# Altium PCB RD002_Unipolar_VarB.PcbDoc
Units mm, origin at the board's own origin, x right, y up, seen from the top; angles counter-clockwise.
Board outline 40 x 14 mm, 2 copper layers (Top Layer, Bottom Layer), stack 1.37 mm thick; 29 components, 15 nets, 67 pads, 26 vias.
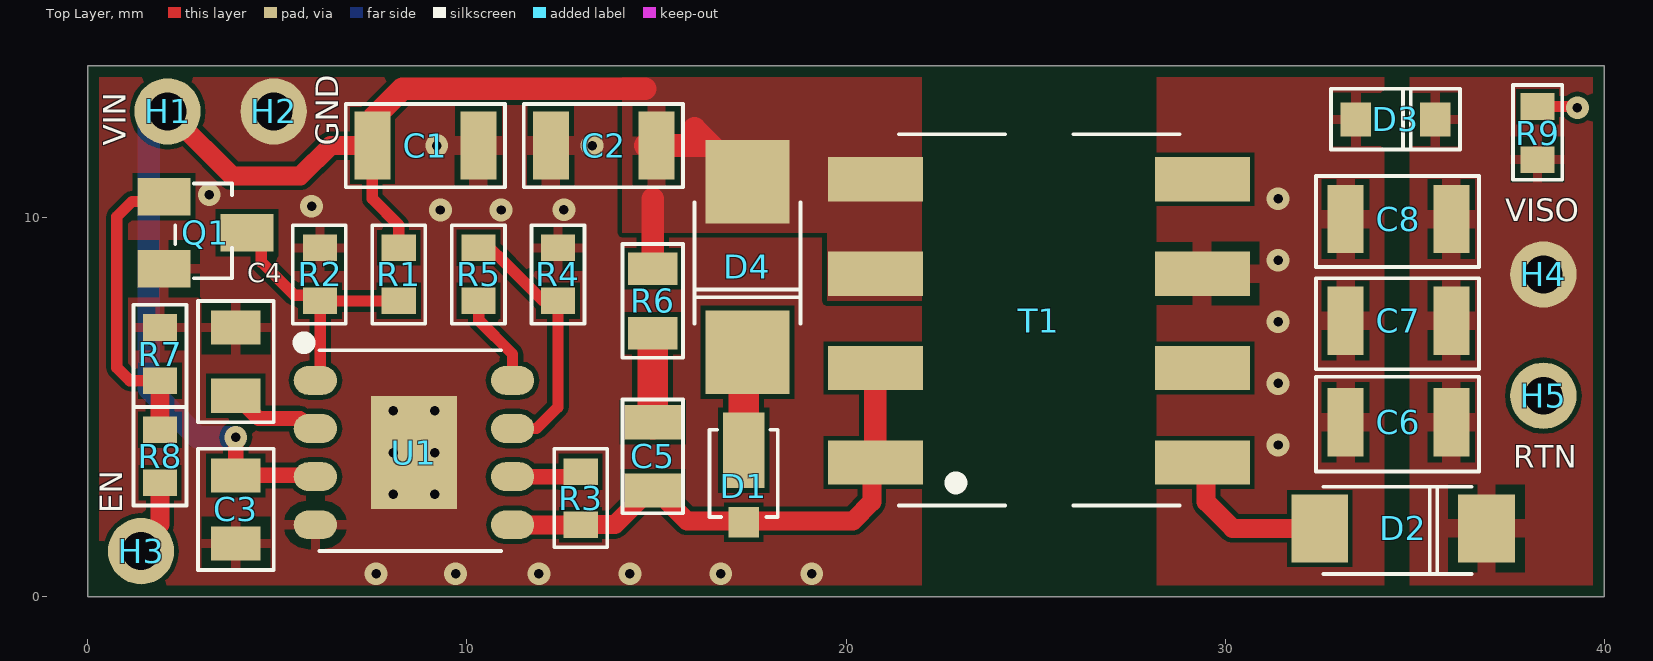
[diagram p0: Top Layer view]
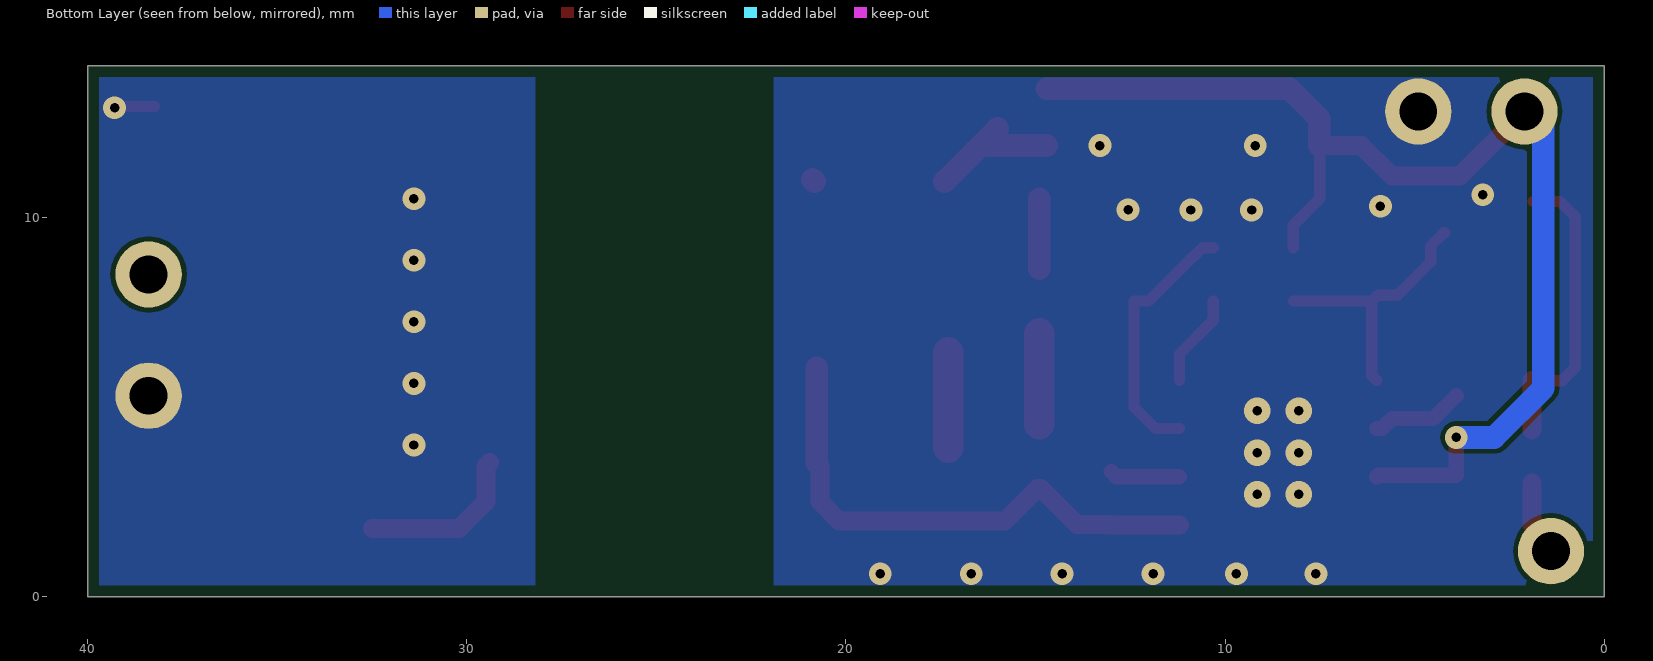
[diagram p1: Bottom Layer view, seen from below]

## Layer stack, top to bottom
Top Solder: solder mask 0.0254, SM-001, Dk 4
Top Layer: signal copper 0.035
Dielectric 1: core 1.3, Core-043, Dk 4.3
Bottom Layer: signal copper 0.035
Bottom Solder: solder mask 0.0254, SM-001, Dk 4

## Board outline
0,0 40,0 40,14 0,14

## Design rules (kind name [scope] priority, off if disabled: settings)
AcuteAngle [All] p1 off: minimum=4.50000000000000E+0001 checktracksonly=FALSE
AssemblyTestPointUsage [All] p1 off: valid=2
AssemblyTestpoint [All] p1 off: testpointundercomponent=TRUE minsize=1.016 maxsize=2.54 preferedsize=1.524 minholesize=0 maxholesize=1.016 preferedholesize=0.813 testpointgrid=0.025 usegrid=TRUE gridtolerance=0 allowsidetop=TRUE allowsidebottom=TRUE
Clearance Clearance_WEDirekt_125u_35u [All] p1: gap=0.125 ignorepadtopadclearanceinfootprint=TRUE except(0.17: SMDPad-SMDPad SMDPad-THPad THPad-THPad)
ComponentClearance "Schematic Component Clearance Constraint 2" [InComponent('NT1')] p1: gap=0 collisioncheckmode=3 verticalgap=0 showdistances=FALSE
ComponentClearance "Schematic Component Clearance Constraint 1" [InComponent('NT2')] p2: gap=0 collisioncheckmode=3 verticalgap=0 showdistances=FALSE
ComponentClearance ComponentClearance_ScrewToNut [(HasFootprint('NY PMS 440 0025 PH')) vs (HasFootprint('Keystone_1902C'))] p3: gap=0 collisioncheckmode=3 verticalgap=0 showdistances=FALSE
ComponentClearance ComponentClearance_testpoint [(HasFootprint('NO BOM TP'))] p4: gap=0 collisioncheckmode=3 verticalgap=0 showdistances=FALSE
ComponentClearance not_comp_1 [WithinRoom('not_comp')] p5: gap=0 collisioncheckmode=3 verticalgap=0 showdistances=FALSE
ComponentClearance ComponentClearance_1 [All] p6: gap=0.254 collisioncheckmode=3 verticalgap=0.254 showdistances=FALSE
ComponentClearance ComponentClearance_Shunt [InComponentClass('Header') vs InComponentClass('Shunt')] p7 off: gap=0 collisioncheckmode=3 verticalgap=0 showdistances=FALSE
ComponentClearance ComponentClearance_Logo [InComponentClass('Logo')] p8: gap=1.27 collisioncheckmode=3 verticalgap=0.254 showdistances=FALSE
ComponentClearance ComponentClearance_MountingHoles [InComponentClass('Mounting Holes')] p9: gap=0 collisioncheckmode=3 verticalgap=2540 showdistances=FALSE
ComponentClearance ComponentClearance_SmallPassives [HasFootprint('0201*') or HasFootprint('0402*') or HasFootprint('0508') or HasFootprint('0603*') or HasFootprint('0612') or HasFootprint('0805*') or HasFootprint('0815*') or HasFootprint('0830*') or HasFootprint('1206*') or HasFootprint('1210*') or HasFootprint('1808*') or HasFootprint('1812*') or HasFootprint('1825*') or HasFootprint('2010*') or HasFootprint('2220*') or HasFootprint('2225*') or HasFootprint('2512*') or HasFootprint('2728*') or HasFootprint('3518*') vs HasFootprint('0201*') or HasFootprint('0402*') or HasFootprint('0508') or HasFootprint('0603*') or HasFootprint('0612') or HasFootprint('0805*') or HasFootprint('0815*') or HasFootprint('0830*') or HasFootprint('1206*') or HasFootprint('1210*') or HasFootprint('1808*') or HasFootprint('1812*') or HasFootprint('1825*') or HasFootprint('2010*') or HasFootprint('2220*') or HasFootprint('2225*') or HasFootprint('2512*') or HasFootprint('2728*') or HasFootprint('3518*')] p10: gap=0.127 collisioncheckmode=3 verticalgap=0.254 showdistances=FALSE
ComponentClearance ComponentClearance_THtoSMT [IsThruComponent vs IsSMTComponent] p11: gap=1.016 collisioncheckmode=3 verticalgap=0.762 showdistances=FALSE
ComponentClearance ComponentClearance_THtoTH [IsThruComponent vs IsThruComponent] p12: gap=3 collisioncheckmode=3 verticalgap=0.762 showdistances=FALSE
DiffPairsRouting [All] p1 off: maxlimit=2.54 minlimit=0.254 mostfreqgap=0.254 toplayer_minwidth=0.381 toplayer_maxwidth=0.381 toplayer_prefwidth=0.381 bottomlayer_minwidth=0.381 bottomlayer_maxwidth=0.381 bottomlayer_prefwidth=0.381 maxuncoupledlength=25.4
FabricationTestPointUsage TestPointUsage [All] p1: valid=2 allowmultiple=FALSE
FabricationTestpoint Testpoint [All] p1: side=3 testpointundercomponent=TRUE minsize=1.016 maxsize=2.54 preferedsize=1.524 minholesize=0 maxholesize=1.016 preferedholesize=0.813 testpointgrid=0.025 allowsidetop=TRUE allowsidebottom=TRUE usegrid=TRUE gridtolerance=0
FanoutControl Fanout_LCC [IsLCC] p1 off: bgadir=Out bgaviamode=Centered fanoutstyle=Auto fanoutdirection=Alternating viagrid=0.025 // Fanout_LCC (Default Rule)
FanoutControl Fanout_BGA [IsBGA] p2: bgadir=Out bgaviamode=Centered fanoutstyle=Auto fanoutdirection=Alternating viagrid=0.025 // Fanout_BGA (Default Rule)
FanoutControl Fanout_Default [All] p4: bgadir=Out bgaviamode=Centered fanoutstyle=Auto fanoutdirection=Alternating viagrid=0.025 // Fanout_Default (Default Rule)
FanoutControl Fanout_Small [(CompPinCount < 5)] p5: bgadir=Out bgaviamode=Centered fanoutstyle=Auto fanoutdirection=OutThenIn viagrid=0.025 // Fanout_Small (Default Rule)
Height [All] p1 off: minheight=0 maxheight=25.4 prefheight=12.7
HoleSize [All] p1: absolutevalues=TRUE maxlimit=1000 minlimit=0.1 maxpercent=80.000 minpercent=20.000
HoleToHoleClearance [All] p1: gap=0.4 allowstackedmicrovias=TRUE
MinimumAnnularRing MinimumAnnularRing_ThermalPadVias [IsVia and InAnyComponent] p1: minimumring=0.174
MinimumAnnularRing [All] p2: minimumring=0.174
MinimumSolderMaskSliver MinimumSolderMaskSliver_Logo [InComponentClass('Logo') vs InComponentClass('Logo')] p1: minsoldermaskwidth=0.018
MinimumSolderMaskSliver [All] p2: minsoldermaskwidth=0.025
PlaneConnect [All] p1: planeconnectstyle=Direct reliefexpansion=0.254 reliefentries=4 reliefconductorwidth=0.254 reliefairgap=0.254
PolygonConnect PolygonConnect_1 [InNet('GND')] p1: connectstyle=Relief reliefconductorwidth=0.254 reliefentries=4 polygonreliefangle="90 Angle" airgapwidth=0.254
PolygonConnect [All] p2: connectstyle=Direct reliefconductorwidth=0.254 reliefentries=4 polygonreliefangle="90 Angle" airgapwidth=0.254
RoutingVias Vias_WEDirekt_125u_35u [IsVia and InAnyComponent] p1: holewidth=0.1 width=0.45 viastyle="Through Hole" minholewidth=0.1 minwidth=0.45 maxholewidth=1 maxwidth=20
RoutingVias [All] p2: holewidth=0.1 width=0.45 viastyle="Through Hole" minholewidth=0.1 minwidth=0.45 maxholewidth=20 maxwidth=20
SMDToCorner [All] p1: distance=30000
SilkToSilkClearance [All] p1 off: silktosilkclearance=0.127
SilkToSolderMaskClearance SilkscreenOverComponentPads [IsPad] p1 off: minsilkscreentomaskgap=0.127 clearancetoexposedcopper=TRUE
SolderMaskExpansion [All] p1: expansion=0.1 istentingtop=FALSE
UnRoutedNet [All] p1: checkbadconnections=TRUE
Width Width_WEDirekt_125u_35u [All] p1: maxlimit=20 minlimit=0.125 preferedwidth=0.5 minimp=50.000000 maximp=50.000000 favimp=50.000000 checkconnectedcopper=TRUE
12 further rules are at their usual default settings.

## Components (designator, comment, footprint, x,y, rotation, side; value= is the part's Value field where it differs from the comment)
C1 "885012108022" C1206 8.9,11.9 r0 top value=10u
C2 "885012108022" C1206 13.6,11.9 r0 top value=10u
C3 "885012207103" C0805#1 3.9,2.3 r90 top value=1u
C4 "885012207103" C0805#1 3.9,6.2 r270 top value=1u
C5 "885012207084" C0805#2 14.9,3.7 r90 top value=470p
C6 "885012108022" C1206 34.57,4.6 r0 top value=10u
C7 "885012108022" C1206 34.57,7.28 r0 top value=10u
C8 "885012108022" C1206 34.57,9.96 r0 top value=10u
D1 "V1PM10-M3" D_DO-219AD_(uSMP) 17.3,3.1 r270 top
D2 "VSSAF3M10-M3" D_DO-221AC_(SMA_Slim) 34.7,1.8 r0 top
D3 "PLZ16BG3H" D_DO-219AC_(uSMF) 34.5,12.6 r0 top
D4 "BZG03C27-M3" D_DO-214AC_(SMA) 17.4,8.7 r270 top
H1 "TH-1MM" PIN-TH-ROUND-1MM#1 2,12.6 r90 top
H2 "TH-1MM" PIN-TH-ROUND-1MM#2 4.7,12.6 r90 top
H3 "TH-1MM" PIN-TH-ROUND-1MM#3 1.4,1.2 r90 top
H4 "TH-1MM" PIN-TH-ROUND-1MM#3 38.4,8.5 r90 top
H5 "TH-1MM" PIN-TH-ROUND-1MM#3 38.4,5.3 r90 top
Q1 "SQ2318AES-T1_BE3" IC_SOT23-3_V 3.1,9.6 r0 top
R1 "RC0603FR-07806KL" R0603 8.2,8.5 r90 top value=806k
R2 "RC0603FR-07232KL" R0603 6.125,8.5 r270 top value=232k
R3 "RT0603FRE0771K5L" R0603 13,2.6 r270 top value=71.5k
R4 "RT0603BRD0710KL" R0603 12.4,8.5 r270 top value=10k
R5 "R0603_DNP" R0603_DNP 10.308,8.5 r90 top value=DNP
R6 "CMP0805-FX-1000ELF" R0805 14.9,7.8 r90 top value=100
R7 "RC0603FR-0710KL" R0603 1.9,6.4 r270 top value=10k
R8 "RC0603FR-073R3L" R0603 1.9,3.7 r90 top value=3.3
R9 "R0603_DNP" R0603_DNP 38.246,12.231 r270 top value=DNP
T1 "750318114" EP7_Extended_Rail 25.085,7.275 r0 top
U1 "LT8302HS8E#WPBF" LT-S8E-8_V 8.6,3.8 r0 top

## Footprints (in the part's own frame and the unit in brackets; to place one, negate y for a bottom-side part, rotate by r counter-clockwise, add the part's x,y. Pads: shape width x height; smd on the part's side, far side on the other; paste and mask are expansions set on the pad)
C0805#1 [mm] "Chip Capacitor, 2-Leads, Body 2.00x1.25mm, IPC Low Density"
  rect 0.9x1.3 smd: 1(-0.9,0) 2(0.9,0)
  body extent -1.1,-0.72 1.1,0.72, height 1.45
C0805#2 [mm] "Chip Capacitor, 2-Leads, Body 2.00x1.25mm, IPC Low Density"
  rect 0.9x1.5 smd: 1(-0.9,0) 2(0.9,0)
  body extent -1.1,-0.72 1.1,0.72, height 1.45
C1206 [mm]
  rect 0.95x1.8 smd: 1(-1.39,0) 2(1.4,0)
  body extent -1.7,-0.9 1.7,0.9, height 1.8
D_DO-214AC_(SMA) [mm] "DO-214AC SMA"
  rect 2.2x2.21 smd paste+0 mask+0: A(-2.25,0) C(2.25,0)
  body extent -3.45,-1.5 3.45,1.5, height 0.25
D_DO-219AC_(uSMF) [mm]
  rect 0.8x0.9 smd: A(-1.05,-0.01) C(1.05,-0.01)
  body extent -1.26,-0.66 1.24,0.64, height 0.6
D_DO-219AD_(uSMP) [mil]
  rect 31.5x31.5 smd: A(44.8,0)
  rect 78.74x43.31 smd: C(-30,0)
  body extent -73,-31 65,31, height 10
D_DO-221AC_(SMA_Slim) [mm] "2-Leads, Body 4.2x2.6mm"
  rect 1.5x1.8 smd: A(-2.2,0) C(2.2,0)
  body extent -2.55,-1.3 2.55,1.3, height 1.1
EP7_Extended_Rail [mm] "SMD, 8-Leads, Body 9.8x7.0mm (max), Pitch 2.49mm, IPC Medium Density"
  rect 2.5x1.17 smd: 1(-4.31,-3.735) 2(-4.31,-1.245) 3(-4.31,1.245) 4(-4.31,3.735) 5(4.32,3.735) 6(4.32,1.245) 7(4.32,-1.245) 8(4.32,-3.735)
  body extent -5.06,-5.65 5.04,5.45, height 11.39
IC_SOT23-3_V [mm] "SOT23, 3-Leads, Body 3.12x1.5mm, Pitch 0.95mm"
  rect 1.4x1 smd: 1(-1.1,0.95) 2(-1.1,-0.95) 3(1.1,0)
  body extent -1.35,-1.56 1.35,1.56, height 1.2
LT-S8E-8_V [mm] "SOIC, 8-Leads, Body 4.9x3.9mm, Pitch 1.27mm, Thermal Pad 3.25x2.26mm, Recommended"
  oval 1.143x0.76 smd: 1(-2.602,1.905) 2(-2.602,0.635) 3(-2.602,-0.635) 4(-2.602,-1.905) 5(2.601,-1.905) 6(2.601,-0.635) 7(2.601,0.635) 8(2.601,1.905)
  rect 2.26x2.99 smd paste-5: 9(0,0)
  body extent -3.01,-2.45 3.01,2.45, height 1.75
PIN-TH-ROUND-1MM#1 [mm] "PIN-TH-ROUND-1MM"
  round 1.75 hole 1: 1(0.2,-0.1)
PIN-TH-ROUND-1MM#2 [mm] "PIN-TH-ROUND-1MM"
  round 1.75 hole 1: 1(0.2,-0.2)
PIN-TH-ROUND-1MM#3 [mm] "PIN-TH-ROUND-1MM"
  round 1.75 hole 1: 1(0,0)
R0603 [mm] "Chip Resistor, Body 1.6x0.8mm, IPC High Density"
  rect 0.7x0.9 smd: 1(-0.7,0) 2(0.7,0)
  body extent -0.85,-0.47 0.85,0.47, height 0.6
R0603_DNP [mm] "Chip Resistor, Body 1.6x0.8mm, IPC High Density"
  rect 0.7x0.9 smd: 1(-0.7,0) 2(0.7,0)
R0805 [mm] "Chip Resistor, Body 2.0x1.3mm, IPC High Density"
  rect 0.85x1.3 smd: 1(-0.85,0) 2(0.85,0)
  body extent -1.1,-0.67 1.1,0.68, height 0.7

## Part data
C1 C2 C6 C7 C8: "MLCC 10uF 50V 10% X7R 1206 General Purpose", MFR="Wurth Elektronik", Package=1206, Voltage=50V
C3 C4: "MLCC 1uF 50V 10% X7R 0805 General Purpose", DC-Voltage=50V, Dielectric=X7R, MFR="Wurth Elektronik", Package=0805, Tolerance=10%
C5: "MLCC SMD 470p 50V 10% X7R 0805 General Purpose", MFR="Wurth Elektronik"
D1: "Schottky Rectifier 1A 100V SMD DO-219AD (uSMP) V1PM10-M3", Current=1A, MFR=Vishay, Package="DO-219AD (uSMP)", Voltage=100V
D2: "Schottky Rectifier 3A 100V SMD DO-221AC (SMA_Slim) VSSAF3M10-M3", Current=3A, MFR=Vishay, Package="DO-221AC (SMA Slim)", Voltage=100V
D3: "Zener 16V 0.5W SMD DO-219AC (uSMF) PLZ16BG3H", MFR=Vishay, Package="DO-219AC (uSMF)", Power=0.5W, Voltage=16V
D4: "Zener 27V 3W DO-214AC (SMA) BZG03C27-M3", MFR=Vishay, Package="DO-214AC (SMA)", Power=3W, Voltage=27V
H1 H2 H3 H4 H5: library part Pin_hole_1mm, "not available"
Q1: "N-Channel MOSFET 40 V SOT23-3", MFR=Vishay
R1: "Thick Film Resistors 806k 1% 0.1W", Case-EIA=0603, Case-Metric=1608, MFR=Yageo, Power="0.1 W", Tolerance="1 %"
R2: "Thick Film Resistors 232k 1% 0.1W", Case-EIA=0603, Case-Metric=1608, MFR=Yageo, Power="0.1 W", Tolerance="1 %"
R3: "Thin Film Resistors 71.5k 0.1% 0.1W 0603 RT0603FRE0771K5L", Case-EIA=0603, Case-Metric=1608, MFR=Yageo, Power="0.1 W", Tolerance="0.1 %"
R4: "Thin Film Resistors 10k 0.1% 0.1W", Case-EIA=0603, Case-Metric=1608, MFR=Yageo, Power="0.1 W", Tolerance="0.1 %"
R5 R9: "Footprint R0603 DNP"
R6: "Thick Film 100 5% 0.5W 0805 High Power CMP0805-FX-1000ELF", Case-EIA=0805, MFR=Bourns, Power="0.5 W", Tolerance="5 %"
R7: "Thick Film Resistors 10k 1% 0.1W", Case-EIA=0603, Case-Metric=1608, MFR=Yageo, Power="0.1 W", Tolerance="1 %"
R8: "Thick Film Resistors 3.3 1% 0.1W", Case-EIA=0603, Case-Metric=1608, MFR=Yageo, Power="0.1 W", Tolerance="1 %"
T1: "WE-AGDT Auxiliary Gate Drive Transformer, EP7, SMT, 9-18Vin, 19Vout, 6W", Input Voltage=9-18V, Interwinding Capacitance=6.8pF, MFR="Wurth Elektronik", Operating Temperature="-40 to +130degC", Output Power=6W, Output Voltage=19V, Switching Frequency=350kHz
U1: "Micropower No-Opto Isolated Flyback Converter, 2.8 to 42 V, -40 to 150 degC, 8-Pin SOIC (S8E), RoHS, AEC-Q100", MFR="Analog Devices / Linear Tech", Output Current="3.6 A", PartNumber=LT8302, Temperature Max="150 degC", Temperature Min="-40 degC"

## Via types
v1: diameter 0.6, hole 0.25, Top Layer to Bottom Layer, 18 vias
v2: diameter 0.7, hole 0.25, Top Layer to Bottom Layer, 6 vias
v3: diameter 0.6/0.6 (per signal layer), hole 0.25, Top Layer to Bottom Layer, 2 vias

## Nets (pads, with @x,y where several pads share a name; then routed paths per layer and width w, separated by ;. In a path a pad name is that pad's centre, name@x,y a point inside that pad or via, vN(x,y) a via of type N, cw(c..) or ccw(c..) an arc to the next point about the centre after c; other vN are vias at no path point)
D_SNB: D1.C D4.C | length 2.5
  Top Layer w0.8: D1.C@17.3,3.925 D4.C@17.3,6.447
EN: H3.1 R8.1 | length 2
  Top Layer w0.5: H3.1 1.4,1.4 1.9,1.9 R8.1
EN-Q1: Q1.1 R7.2 R8.2 | length 7.8
  Top Layer w0.3: Q1.1@1.875,10.425 1.163,10.425 0.763,10.025 0.763,6.037 1.1,5.7 R7.2
  Top Layer w0.5: R8.2 R7.2
EN/UVLO: Q1.3 R1.1 R2.2 U1.1 | length 7.1
  Top Layer w0.3: Q1.3 4.224,9.6 4.574,9.25 4.574,8.826 5.444,7.956 5.969,7.956 R2.2 ; U1.1 6.125,5.832 R2.2 ; R1.1 R2.2
GND: C1.2 C2.1 C3.1 C4.1 H2.1 Q1.2 R2.1 R4.1 R7.1 U1.4 U1.9
  other v1: 7.6,0.6 9.698,0.601 11.898,0.601 14.298,0.601 16.698,0.601 19.098,0.601 9.298,10.201 10.898,10.201 12.559,10.21 5.898,10.301 3.198,10.601 9.2,11.9 13.3,11.9
  other v2: 8.05,2.7 9.15,2.7 8.05,3.8 9.15,3.8 8.05,4.9 9.15,4.9
GND_ISO: C6.1 C7.1 C8.1 D3.A H5.1 R9.1 T1.6 | length 1.1
  Top Layer w0.3: R9.1 39.269,12.931 v3(39.3,12.9)
  other v1: 31.4,4 31.4,5.625 31.4,7.25 31.4,8.875 31.4,10.5
INTVCC: C4.2 U1.2 | length 2.5
  Top Layer w0.4: C4.2 4.5,4.7 5.593,4.7 5.858,4.435 U1.2
R_SNB: C5.2 R6.1 | length 2.4
  Top Layer w0.8: C5.2@14.9,4.55 R6.1
RFB: R3.1 U1.6 | length 1.9
  Top Layer w0.406: U1.6 12.865,3.165 R3.1
RREF: R4.2 R5.2 U1.7 | length 6.9
  Top Layer w0.3: R5.2 10.6,9.2 10.8,9 10.81,9 12.01,7.8 12.4,7.8 12.4,5 11.835,4.435 U1.7
SEC_D2: D2.A T1.8 | length 4.4
  Top Layer w0.5: T1.8 29.502,3.443 29.502,2.498 30.2,1.8 D2.A
SW: C5.1 D1.A R3.2 T1.1 T1.2 U1.5 | length 14
  Top Layer w0.5: U1.5 12.995,1.895 R3.2 13.9,1.9 14.85,2.85 14.9,2.85 14.95,2.85 15.8,2 17.3,2 20.186,2 20.684,2.498 20.684,3.449 T1.1
  Top Layer w0.6: T1.1 T1.2
TC: R5.1 U1.8 | length 2.5
  Top Layer w0.3: R5.1 10.308,7.292 11.201,6.399 U1.8
V_ISO: C6.2 C7.2 C8.2 D2.C D3.C H4.1 R9.2
VIN: C1.1 C2.2 C3.2 D4.A H1.1 R1.2 R6.2 T1.3 T1.4 U1.3 | length 36.8
  Top Layer w0.254: T1.4@20.666,11.006 T1.4@20.773,10.9
  Top Layer w0.3: C1.1 7.5,11.89 7.5,10.5 8.2,9.8 R1.2
  Top Layer w0.406: v3(3.9,4.2) C3.2 5.963,3.2 U1.3
  Top Layer w0.5: H1.1@2,12.6 2.3,12.6 3.8,11.1 5.6,11.1 6.4,11.9 C1.1@7.5,11.9
  Top Layer w0.6: C1.1 7.51,12.61 8.3,13.4 14.7,13.4 ; C2.2@14.7,11.9 C2.2 16.445,11.9 D4.A@16.595,11.75 ; R6.2 14.9,10.5 ; 16,12.35 16.595,11.755 D4.A@16.595,11.75 ; D4.A 17.395,10.95 D4.A@16.595,11.75
  Top Layer w0.61: T1.4@20.829,10.956 T1.4@20.881,11.009
  Bottom Layer w0.406: H1.1@2.035,12.4 H1.1@2.235,12.2
  Bottom Layer w0.6: H1.1@1.6,12.4 1.6,5.5 2.9,4.2 v3(3.9,4.2)
pads on no net: T1.5 T1.7

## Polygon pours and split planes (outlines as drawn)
GND on Top Layer "GND_TOP" (solid, pour order 95): 0.3,0.3 22,0.3 22,13.7 0.3,13.7
GND_ISO on Top Layer "RTN_TOP" (solid, pour order 94): 28.2,13.7 34.2,13.7 34.2,0.3 28.2,0.3
VIN on Top Layer "VIN_TOP" (solid, pour order 80): 19.5,9.6 14.1,9.6 14.1,13.7 22,13.7 22,7.8 19.5,7.8
V_ISO on Top Layer "VISO_TOP" (solid, pour order 81): 34.88,13.7 39.7,13.7 39.7,0.3 34.88,0.3
GND on Bottom Layer "GND_BOT" (solid, pour order 92): 0.3,13.7 21.9,13.7 21.9,0.3 0.3,0.3
GND_ISO on Bottom Layer "RTN_BOT" (solid, pour order 90): 28.2,13.7 39.7,13.7 39.7,0.3 28.2,0.3

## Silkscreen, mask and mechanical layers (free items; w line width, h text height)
Top Overlay:
  circle w0.5: c5.7,6.7 r0.05
  circle w0.5: c22.9,3 r0.05
  lines w0.1: 2.3,9.3 2.3,9.8 ; 2.8,8.4 3.2,8.4 3.6,8.4 3.8,8.4 3.8,9.2 ; 2.8,10.9 3.3,10.9 3.8,10.9 3.8,10.6 ; 6.1,1.2 10.9,1.2 ; 6.1,6.5 10.9,6.5 ; 16,7.2 16,10.4 ; 16,7.9 18.8,7.9 ; 16,8.1 18.8,8.1 ; 16.6,4.4 16.4,4.4 16.4,2.1 16.7,2.1 ; 17.9,2.1 18.2,2.1 18.2,4.4 18,4.4 ; 18.8,7.2 18.8,10.4 ; 21.4,2.4 24.2,2.4 ; 21.4,12.2 24.2,12.2 ; 26,2.4 28.8,2.4 ; 26,12.2 28.8,12.2 ; 32.6,0.6 36.5,0.6 ; 32.6,2.9 36.5,2.9 ; 34.7,11.8 34.7,13.4 ; 34.7,12.1 34.7,13.1 ; 34.9,11.8 34.9,13.4 ; 34.9,12.1 34.9,13.1 ; 35.4,0.6 35.4,2.9 ; 35.6,0.6 35.6,2.9 ; 1.2,5 2.6,5 ; 1.2,5 1.2,7.7 2.6,7.7 2.6,5 ; 1.2,5 2.6,5 ; 1.2,5 1.2,2.4 2.6,2.4 2.6,5 ; 2.9,0.7 4.9,0.7 4.9,3.9 2.9,3.9 2.9,0.7 ; 2.9,4.6 2.9,7.8 4.9,7.8 4.9,4.6 2.9,4.6 ; 5.4,7.2 6.8,7.2 6.8,9.8 5.4,9.8 5.4,7.2 ; 6.8,10.8 11,10.8 11,13 6.8,13 6.8,10.8 ; 7.5,7.2 8.9,7.2 8.9,9.8 7.5,9.8 7.5,7.2 ; 9.6,7.2 11,7.2 11,9.8 9.6,9.8 9.6,7.2 ; 11.5,10.8 15.7,10.8 15.7,13 11.5,13 11.5,10.8 ; 11.7,7.2 13.1,7.2 13.1,9.8 11.7,9.8 11.7,7.2 ; 12.3,1.3 13.7,1.3 13.7,3.9 12.3,3.9 12.3,1.3 ; 14.1,2.2 15.7,2.2 15.7,5.2 14.1,5.2 14.1,2.2 ; 14.1,6.3 14.1,9.3 15.7,9.3 15.7,6.3 14.1,6.3 ; 32.4,3.3 36.7,3.3 36.7,5.8 32.4,5.8 32.4,3.3 ; 32.4,6 36.7,6 36.7,8.4 32.4,8.4 32.4,6 ; 32.4,8.7 32.4,11.1 36.7,11.1 36.7,8.7 32.4,8.7 ; 32.8,11.8 32.8,13.4 36.2,13.4 36.2,11.8 32.8,11.8 ; 37.6,11 37.6,13.5 38.9,13.5 38.9,11 37.6,11
  text "VIN" at 1,11.9 h0.6 r90
  text "GND" at 6.6,11.9 h0.6 r90
  text "VISO" at 37.4,9.9 h0.6
  text "RTN" at 37.6,3.4 h0.6
  text "EN" at 0.9,2.2 h0.6 r90
Board Outline:
  the board outline again, w0.1
Dimensions:
  text "DIMENSIONS IN MILLIMETER (mm)" at -5.5,-9.5 h2
  text "DIMENSIONS" at -25,-27.83 h2
Title Sheet:
  drawing of 1465 lines, arcs and shapes, not listed
  text "1" at -50.963,228.431 h1.78
  text "2" at -1.924,228.431 h1.78
  text "3" at 47.335,228.431 h1.78
  text "4" at 96.628,228.431 h1.78
  text "5" at 145.904,228.431 h1.78
  text "6" at 194.926,228.431 h1.78
  text "7" at 244.456,228.431 h1.78
  text "8" at 293.478,228.431 h1.78
  text "Layer" at -53.46,205.76 h1.49
  text "Name" at -43.278,205.76 h1.49
  text "Material" at -10.28,205.76 h1.49
  text "Thickness" at 4.614,205.76 h1.49
  text "Constant" at 20.748,205.76 h1.49
  text "Board Layer Stack" at 34.898,205.76 h1.49
  text "Top Overlay" at -43.278,202.783 h1.49
  text "Top Solder" at -43.278,199.806 h1.49
  text "SM-001" at -10.28,199.806 h1.49
  text "0,025mm" at 5.978,199.806 h1.49
  text "4" at 20.748,199.806 h1.49
  text "Top Surface Finish" at -43.278,196.828 h1.49
  text "PbSn" at -10.28,196.828 h1.49
  text "0,020mm" at 5.978,196.828 h1.49
  text "A" at -73.095,194.446 h1.78
  text "A" at 315.525,194.446 h1.78
  text "1" at -53.46,193.851 h1.49
  text "Top Layer" at -43.278,193.851 h1.49
  text "CF-004" at -10.28,193.851 h1.49
  text "0,035mm" at 5.978,193.851 h1.49
  text "Dielectric 1" at -43.278,190.874 h1.49
  text "Core-043" at -10.28,190.874 h1.49
  text "1,300mm" at 6.102,190.874 h1.49
  text "4.3" at 20.748,190.874 h1.49
  text "2" at -53.46,187.897 h1.49
  text "Bottom Layer" at -43.278,187.897 h1.49
  text "CF-004" at -10.28,187.897 h1.49
  text "0,035mm" at 5.978,187.897 h1.49
  text "Bottom Surface Finish" at -43.278,184.92 h1.49
  text "PbSn" at -10.28,184.92 h1.49
  text "0,020mm" at 5.978,184.92 h1.49
  text "Bottom Solder" at -43.278,181.943 h1.49
  text "SM-001" at -10.28,181.943 h1.49
  text "0,025mm" at 5.978,181.943 h1.49
  text "4" at 20.748,181.943 h1.49
  text "Bottom Overlay" at -43.278,178.966 h1.49
  text "Total board thickness:" at -53.46,175.989 h1.49
  text "1,460mm" at 6.102,175.989 h1.49
  text "B" at -73.095,123.834 h1.78
  text "B" at 315.525,123.834 h1.78
  text "C" at -73.095,53.222 h1.78
  text "C" at 315.525,53.222 h1.78
  text "D" at -73.095,-16.882 h1.78
  text "D" at 315.525,-16.882 h1.78
  text "TITLE:" at 173,-26.08 h2
  text "RD002 Unipolar" at 184,-26.08 h2
  text "Eleazar Falco" at 188,-31.83 h2
  text "ENGINEER:" at 173,-32.08 h2
  text "04/2022" at 183,-38.08 h1.78
  text "DATE:" at 173,-38.18 h2
  text "N/A" at 186.25,-43.58 h2
  text "REV:" at 205.5,-43.58 h2
  text "22a" at 213.25,-43.58 h2
  text "N/A" at 253.25,-43.58 h2
  text "VERSION:" at 173,-43.68 h2
  text "ASSY VARIANT:" at 230.9,-43.68 h2
  text "1" at -50.963,-48.429 h1.78
  text "2" at -1.924,-48.429 h1.78
  text "3" at 47.335,-48.429 h1.78
  text "4" at 96.628,-48.429 h1.78
  text "5" at 145.904,-48.429 h1.78
  text "6" at 194.926,-48.429 h1.78
  text "7" at 244.456,-48.429 h1.78
  text "8" at 293.478,-48.429 h1.78
Drill Drawing:
  lines w0.254: -58.527,42.338 -56.834,42.338 -56.834,44.032 -58.527,44.032 -58.527,42.338 ; -58.527,46.148 -57.681,46.572 -56.834,46.148 -57.257,46.995 -56.834,47.842 -57.681,47.418 -58.527,47.842 -58.104,46.995 -58.527,46.148 ; -58.527,50.382 -58.104,50.382 -57.681,49.958 -57.257,50.382 -56.834,50.382 -57.257,50.805 -56.834,51.228 -57.257,51.228 -57.681,51.652 -58.104,51.228 -58.527,51.228 -58.104,50.805 -58.527,50.382
  lines w0.381: -60.046,41.195 156.709,41.195 ; -60.046,52.625 156.709,52.625 ; -46.054,37.385 -46.054,56.435 ; -32.595,37.385 -32.595,56.435 ; -4.409,37.385 -4.409,56.435 ; 8.44,37.385 8.44,56.435 ; 27.078,37.385 27.078,56.435 ; 65.167,37.385 65.167,56.435 ; 80.149,37.385 80.149,56.435 ; 99.092,37.385 99.092,56.435 ; 121.083,37.385 121.083,56.435 ; -60.046,37.385 156.709,37.385 156.709,56.435 -60.046,56.435 -60.046,37.385
  text "Symbol" at -57.76,53.768 h1.83
  text "Count" at -44.911,53.768 h1.83
  text "Hole Size" at -31.452,53.768 h1.83
  text "Plated" at -3.266,53.768 h1.83
  text "Hole Type" at 9.583,53.768 h1.83
  text "Drill Layer Pair" at 28.221,53.768 h1.83
  text "Via/Pad" at 66.31,53.768 h1.83
  text "Pad Shape" at 81.292,53.768 h1.83
  text "Hole Length" at 100.235,53.768 h1.83
  text "Routed Path Length" at 122.226,53.768 h1.83
  text "2" at -44.911,49.958 h1.52
  text "0,250mm (9,84mil)" at -31.452,49.958 h1.52
  text "PTH" at -3.266,49.958 h1.52
  text "Round" at 9.583,49.958 h1.52
  text "Top Layer - Bottom Layer" at 28.221,49.958 h1.52
  text "Via" at 66.31,49.958 h1.52
  text "Rounded" at 81.292,49.958 h1.52
  text "-" at 100.235,49.958 h1.52
  text "-" at 122.226,49.958 h1.52
  text "24" at -44.911,46.148 h1.52
  text "0,250mm (9,84mil)" at -31.452,46.148 h1.52
  text "PTH" at -3.266,46.148 h1.52
  text "Round" at 9.583,46.148 h1.52
  text "Top Layer - Bottom Layer" at 28.221,46.148 h1.52
  text "Via" at 66.31,46.148 h1.52
  text "Rounded" at 81.292,46.148 h1.52
  text "-" at 100.235,46.148 h1.52
  text "-" at 122.226,46.148 h1.52
  text "5" at -44.911,42.338 h1.52
  text "1,000mm (39,37mil)" at -31.452,42.338 h1.52
  text "PTH" at -3.266,42.338 h1.52
  text "Round" at 9.583,42.338 h1.52
  text "Top Layer - Bottom Layer" at 28.221,42.338 h1.52
  text "Pad" at 66.31,42.338 h1.52
  text "Rounded" at 81.292,42.338 h1.52
  text "-" at 100.235,42.338 h1.52
  text "-" at 122.226,42.338 h1.52
  text "31 Total" at -44.911,38.528 h1.52
  text "DRILL Guide" at -22,-27.83 h2
Gerber Print:
  drawing of 1652 lines, arcs and shapes, not listed
  text "ARTWORK VIEWED FROM TOP SIDE OF BOARD" at -28.75,-19.58 h1.6
  text "BOARD NAME:" at -39,-23.83 h2
  text "RD002 Unipolar" at -16,-23.83 h2
  text "LAYER:" at -39,-28.08 h2
  text "REV:" at -0.76,-32 h2
  text "22a" at 7.47,-32.07 h2
  text "SCALE:" at 22,-32.08 h2
  text "2:1" at 35,-32.08 h2
  text "VERSION:" at -39,-32.33 h2
  text "B" at -22.5,-32.33 h2
  text "GENERATED:" at -39,-36.58 h2
  text "04/2022" at -16,-36.58 h2
  text "(c) Wurth Elektronik eiSos Group        www.we-online.de" at -40,-41.08 h2
Assembly Notes:
  lines w0.1: 186.75,25.42 303.75,25.42 ; 186.75,33.42 303.75,33.42 ; 186.75,49.42 303.75,49.42 303.75,82.42 186.75,82.42 186.75,96.42 ; 186.75,125.42 303.75,125.42 ; 186.75,142.42 303.75,142.42 ; 186.75,161.42 303.75,161.42 ; 186.83,7.17 303.83,7.17 ; 191.75,-8.58 296.75,-8.58 ; 191.75,-1.58 296.75,-1.58 ; 223.75,180.42 236.75,180.42 ; 223.75,188.42 236.75,188.42 ; 249.75,165.42 262.75,165.42 ; 249.75,171.42 262.75,171.42 ; 278.75,69.42 296.75,69.42 ; 278.75,85.42 296.75,85.42 ; 278.75,93.42 296.75,93.42 ; 278.75,111.42 296.75,111.42 ; 280.75,180.42 293.75,180.42 ; 280.75,188.42 293.75,188.42 ; 186.75,-14.58 303.75,-14.58 303.75,215.42 198.75,215.42 186.75,215.42 186.75,-14.58 ; 186.75,107.42 303.75,107.42 186.75,107.42 ; 186.75,203.42 303.75,203.42 186.75,203.42 ; 194.75,37.42 197.75,37.42 197.75,40.42 194.75,40.42 194.75,37.42 ; 194.75,70.42 197.75,70.42 197.75,73.42 194.75,73.42 194.75,70.42 ; 194.75,94.42 197.75,94.42 197.75,97.42 194.75,97.42 194.75,94.42 ; 194.75,111.42 197.75,111.42 197.75,114.42 194.75,114.42 194.75,111.42 ; 212.75,70.42 215.75,70.42 215.75,73.42 212.75,73.42 212.75,70.42 ; 218.75,86.42 221.75,86.42 221.75,89.42 218.75,89.42 218.75,86.42 ; 218.75,94.42 221.75,94.42 221.75,97.42 218.75,97.42 218.75,94.42 ; 218.75,111.42 221.75,111.42 221.75,114.42 218.75,114.42 218.75,111.42 ; 222.75,145.42 225.75,145.42 225.75,148.42 222.75,148.42 222.75,145.42 ; 222.75,150.42 225.75,150.42 225.75,153.42 222.75,153.42 222.75,150.42 ; 222.75,155.42 225.75,155.42 225.75,158.42 222.75,158.42 222.75,155.42 ; 225.75,37.42 228.75,37.42 228.75,40.42 225.75,40.42 225.75,37.42 ; 242.75,69.42 245.75,69.42 245.75,72.42 242.75,72.42 242.75,69.42 ; 243.75,86.42 246.75,86.42 246.75,89.42 243.75,89.42 243.75,86.42 ; 243.75,94.42 246.75,94.42 246.75,97.42 243.75,97.42 243.75,94.42 ; 243.75,111.42 246.75,111.42 246.75,114.42 243.75,114.42 243.75,111.42 ; 255.75,37.42 258.75,37.42 258.75,40.42 255.75,40.42 255.75,37.42 ; 258.75,28.42 261.75,28.42 261.75,31.42 258.75,31.42 258.75,28.42 ; 259.75,148.42 262.75,148.42 262.75,151.42 259.75,151.42 259.75,148.42 ; 259.75,152.42 262.75,152.42 262.75,155.42 259.75,155.42 259.75,152.42 ; 273.75,166.42 276.75,166.42 276.75,169.42 273.75,169.42 273.75,166.42 ; 273.75,170.42 276.75,170.42 276.75,173.42 273.75,173.42 273.75,170.42 ; 276.75,28.42 279.75,28.42 279.75,31.42 276.75,31.42 276.75,28.42
  text "FABRICATION NOTES" at 220.05,207.42 h3
  text "MINIMUM SIZE CONSTRAINTS" at 220.75,197.42 h2
  text "TRACK WIDTH (MIN):" at 189.75,189.42 h2
  text "0.3  mm" at 227.75,189.42 h2
  text "CLEARANCE (MIN):" at 249.75,189.42 h2
  text "0.125 mm" at 283.39,189.24 h2
  text "DRILL DIAM.(MIN):" at 189.75,181.42 h2
  text "0.25  mm" at 227.75,181.42 h2
  text "PAD SIZE (MIN):" at 249.75,181.42 h2
  text "XXXX mm" at 284.75,181.42 h2
  text "0.6 mm" at 253.75,172.42 h2
  text "x" at 274.55,171.22 h2
  text "EXTERNAL" at 278.75,170.42 h2
  text "ANNULAR RING DIAMETER (MIN):" at 189.75,169.42 h2
  text "N/A mm" at 253.75,166.42 h2
  text "INTERNAL" at 278.75,166.42 h2
  text "VIAS DETAILS:" at 189.75,156.42 h2
  text "VIAS IN PAD" at 227.75,155.42 h2
  text "CONDUCTIVE FILL" at 264.75,152.42 h2
  text "TENTED VIAS" at 227.75,150.42 h2
  text "NON-CONDUCTIVE FILL" at 264.75,148.42 h2
  text "FILLED VIAS" at 227.75,145.42 h2
  text "FURTHER VIA DETAILS IN DRAWING ATTACHED" at 189.75,136.42 h2
  text "DRILL AND HOLES DETAILS SEE ADJACENT TABLE" at 189.75,132.42 h2
  text "SUBSTRATE MATERIAL AND LAYER STACK-UP SEE ADJACENT TABLE" at 189.75,128.42 h2
  text "SURFACE FINISH PLATING" at 189.75,120.42 h2
  text "ENIG" at 199.75,112.42 h2
  text "ImAg" at 224.25,112.42 h2
  text "ImSn" at 248.75,112.42 h2
  text "OTHER:" at 266.75,112.42 h2
  text "x" at 195.35,112.12 h2
  text "SOLDER MASK COLOR:" at 189.75,102.42 h2
  text "x" at 195.55,95.22 h2
  text "RED" at 199.75,94.42 h2
  text "GREEN" at 224.25,94.42 h2
  text "BLUE" at 248.75,94.42 h2
  text "OTHER:" at 266.75,94.42 h2
  text "x" at 244.6,87.12 h2
  text "FINISH:" at 195.75,86.42 h2
  text "MATTE" at 224.25,86.42 h2
  text "GLOSS" at 248.75,86.42 h2
  text "OTHER:" at 266.75,86.42 h2
  text "SILKSCREEN:" at 202.75,77.42 h2
  text "SILKSCREEN COLOR:" at 246.75,77.42 h2
  text "x" at 195.65,71.32 h2
  text "x" at 213.65,71.32 h2
  text "TOP" at 199.75,70.42 h2
  text "BOTTOM" at 217.75,70.42 h2
  text "WHITE" at 247.75,70.42 h2
  text "OTHER:" at 266.75,70.42 h2
  text "x" at 243.55,70.22 h2
  text "NOTES:" at 197.75,61.42 h2
  text "SILKSCREEN LOCATION AS PER GERBER FILE XXX" at 212.75,61.42 h2
  text "NO SILKSCREEN ON EXPOSED CONDUCTIVE PADS" at 212.75,57.42 h2
  text "USE PERMANENT NON-CONDUCTIVE INK" at 212.75,53.42 h2
  text "ARRAY-PANELIZATION CUT-OUT" at 219.75,44.42 h2
  text "x" at 256.7,38.2 h2
  text "V-SCORE" at 199.75,37.42 h2
  text "NC-ROUTE" at 230.75,37.42 h2
  text "LOOSE (CUT AND TRIM)" at 260.75,37.42 h2
  text "x" at 259.55,29.22 h2
  text "ELECTRICAL TEST REQUIRED:" at 189.75,28.42 h2
  text "YES" at 263.75,28.42 h2
  text "NO" at 281.75,28.42 h2
  text "ADDITIONAL REQUIREMENTS NOT SPECIFIED SHALL MEET OR EXCEED IPC-6012 CLASS-B SPECIFICATION" at 189.5,17.842 h2 r0.04
  text "ACCEPTANCE CRITERIA AS PER IPC-600 CLASS B" at 189.75,14.92 h2
  text "RoHS COMPLIANCE" at 190,11.92 h2
  text "ADDITIONAL INFORMATION:" at 194,2.92 h2
Top_Print_Gerber:
  text "TOP Route" at -25,-28.08 h2
Int1_Print_Gerber:
  text "INT1 Layer Route" at -25,-28.08 h2
Int2_Print_Gerber:
  text "INT2 Layer Route" at -24,-28.08 h2
Bottom_Print_Gerber:
  text "BOTTOM ROUTE" at -25,-28.08 h2
TopPaste_Print_Gerber:
  text "TOP Paste" at -25,-28.15 h2
BottomPaste_Print_Gerber:
  text "BOTTOM Paste" at -25,-28.08 h2
TopSolder_Print_Gerber:
  text "TOP Soldermask" at -25,-28.08 h2
BottomSolder_Print_Gerber:
  text "BOTTOM Soldermask" at -25,-28.08 h2
Top_Reference_Print_Gerber:
  text "TOP Assembly Reference" at -25,-28.08 h2
Top_Silkscreen_Print_Gerber:
  text "TOP Silkscreen" at -25,-27.83 h2
Bottom_Silkscreen_Print_Gerber:
  text "BOTTOM Silkscreen" at -25,-28.08 h2
Bottom_Reference_Print_Gerber:
  text "BOTTOM Assembly Reference" at -25,-28.08 h2

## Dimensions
0,0 to 0,14 on Dimensions
0,0 to 40,0 on Dimensions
